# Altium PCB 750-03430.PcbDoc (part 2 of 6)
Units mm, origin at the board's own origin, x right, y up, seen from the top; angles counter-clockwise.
Board outline 141.61 x 63.5 mm, 6 copper layers (Top Layer, L2, L3, L4, L5, Bottom Layer), stack 1.557 mm thick; 401 components, 285 nets, 1356 pads, 1712 vias.
Unrouted connection lines stored in the file: 45.
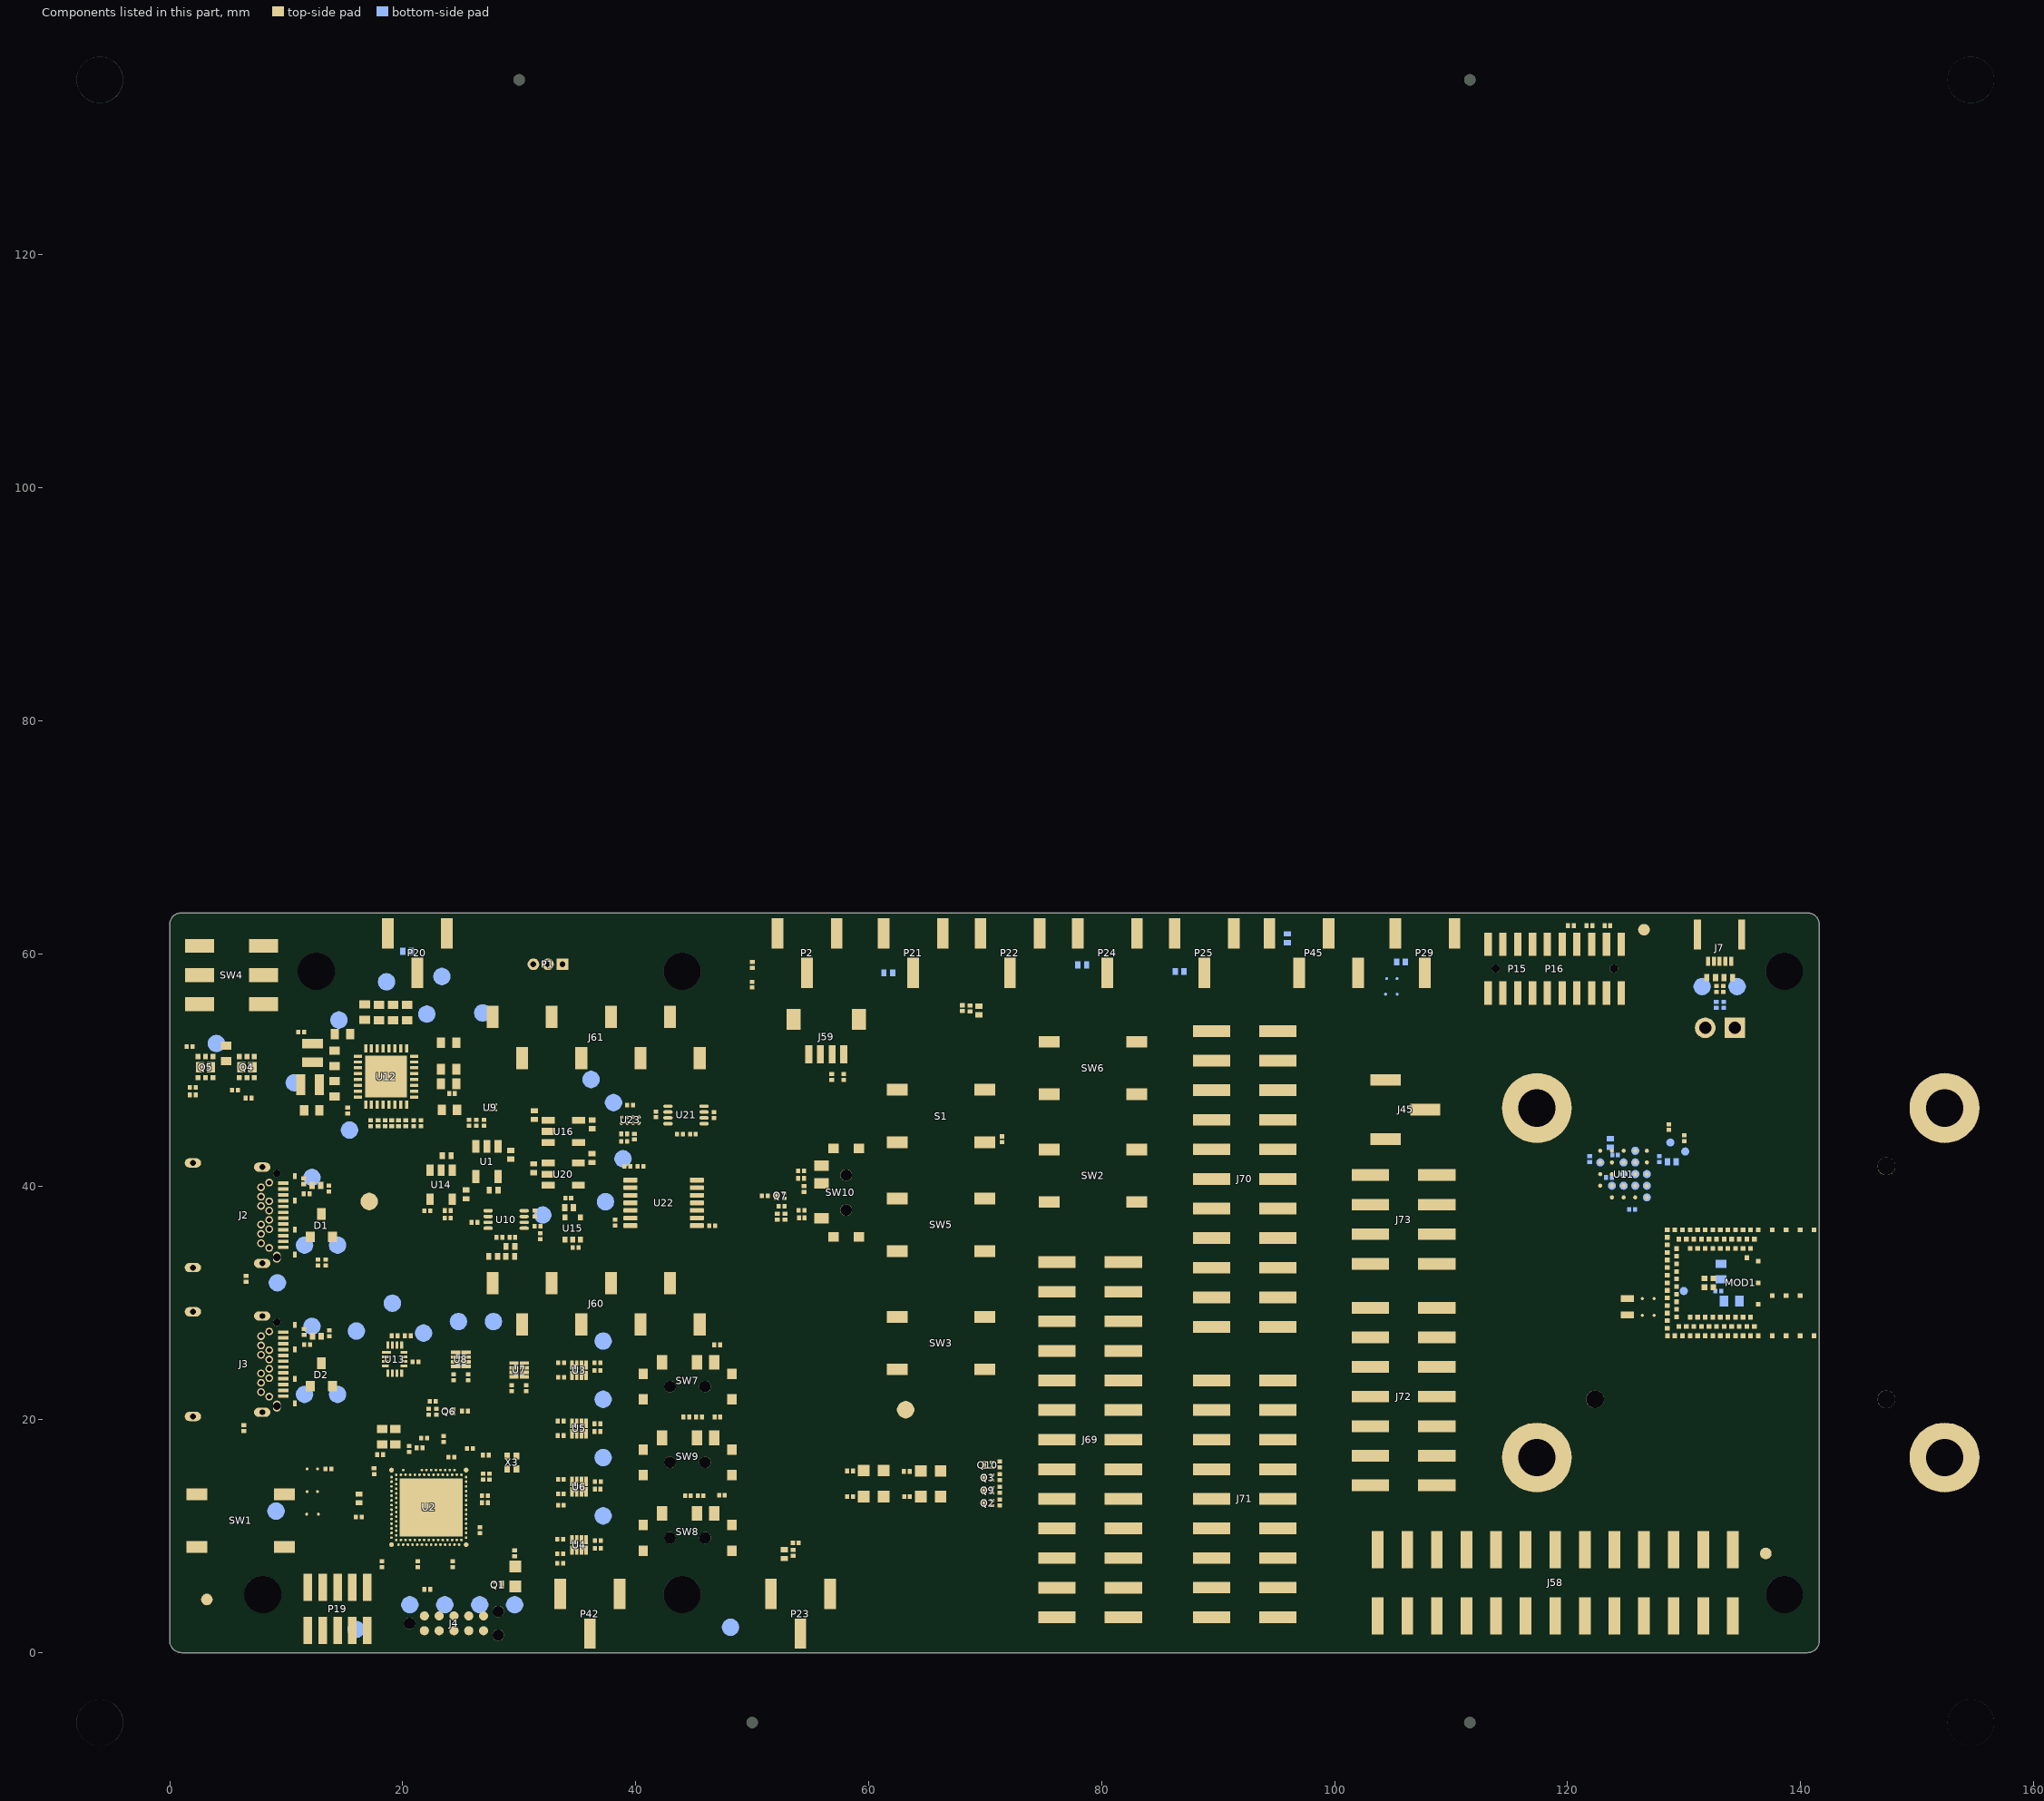
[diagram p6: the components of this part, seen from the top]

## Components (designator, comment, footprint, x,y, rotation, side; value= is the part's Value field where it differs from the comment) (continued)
TP45 "SMT, 1.5mm, Test Pad" "Test Point, SMT 1.5mm Round" 37.208,26.746 r180 bottom
TP46 "SMT, 1.5mm, Test Pad" "Test Point, SMT 1.5mm Round" 37.208,11.746 r180 bottom
TP51 "SMT, 1.5mm, Test Pad" "Test Point, SMT 1.5mm Round" 37.208,21.746 r180 bottom
TP52 "SMT, 1.5mm, Test Pad" "Test Point, SMT 1.5mm Round" 37.208,16.746 r180 bottom
TP58 "SMT, 1.5mm, Test Pad" "Test Point, SMT 1.5mm Round" 27.79,28.423 r270 bottom
TP59 "SMT, 1.5mm, Test Pad" "Test Point, SMT 1.5mm Round" 24.79,28.423 r270 bottom
TP60 "SMT, 1.5mm, Test Pad" "Test Point, SMT 1.5mm Round" 32.026,37.567 r180 bottom
TP61 "SMT, 1.5mm, Test Pad" "Test Point, SMT 1.5mm Round" 21.79,27.432 r270 bottom
TP62 "SMT, 1.5mm, Test Pad" "Test Point, SMT 1.5mm Round" 9.126,12.15 r180 bottom
TP73 "SMT, 1.5mm, Test Pad" "Test Point, SMT 1.5mm Round" 23.365,58.039 r180 bottom
TP82 "SMT, 1.5mm, Test Pad" "Test Point, SMT 1.5mm Round" 19.115,29.997 r180 bottom
TP84 "SMT, 0.7mm, Test Pad" "Test Point, SMT 0.7mm Round" 129.972,31.045 r90 bottom
TP87 "SMT, 1.5mm, Test Pad" "Test Point, SMT 1.5mm Round" 14.526,54.305 r90 bottom
TP88 "SMT, 1.5mm, Test Pad" "Test Point, SMT 1.5mm Round" 22.07,54.813 r0 bottom
U1 "On Semiconductor, NCV8114ASN180T1G" "SOT23_5, Height 1.1mm" 27.234,42.173 r270 top value=NCV8114ASN180T1G
U2 "Nordic, nRF5340-QKAA" "Nordic, nRF5340-QKAA" 22.445,12.474 r0 top value=nRF5340-QKAA
U3 "TI, TXB0302DQMR" "X2SON, 8-Leads, SMD" 35.145,24.246 r90 top value=TXB0302DQMR
U4 "TI, TXB0302DQMR" "X2SON, 8-Leads, SMD" 35.145,9.246 r90 top value=TXB0302DQMR
U5 "TI, TXB0302DQMR" "X2SON, 8-Leads, SMD" 35.145,19.246 r90 top value=TXB0302DQMR
U6 "TI, TXB0302DQMR" "X2SON, 8-Leads, SMD" 35.145,14.246 r90 top value=TXB0302DQMR
U7 "TI, TXB0302DQMR" "X2SON, 8-Leads, SMD" 29.995,24.264 r180 top value=TXB0302DQMR
U8 "TI, TXB0302DQMR" "X2SON, 8-Leads, SMD" 24.995,25.171 r180 top value=TXB0302DQMR
U9 "Toshiba, TCK111G,LF" "WLCSP-6, 1.0mm x 1.5mm, 0.5mm pitch" 27.51,46.795 r270 top value=TCK111G,LF
U10 "TI, TXB0102DCUR" VFSOP8_2x2.3 28.881,37.186 r270 top value=TXB0102DCUR
U11 "Macronix, MX25UW6345GXDI00" "BGA 24, 6mmx8mm, Hight 1.2mm" 124.803,41.079 r90 top value=MX25UW6345GXDI00
U12 "Nordic, nPM1300-QEAA" "QFN32, 5x5, Pitch 0.5mm, Height 1mm" 18.574,49.45 r0 top value=nPM1300-QEAA
U13 "ON Semi, FSA2466UMX" "UQFN16, 2.6x1.8, Pitch 0.4mm, Height 0.5mm" 19.316,25.196 r0 top value=FSA2466UMX
U14 "Richtek, RT9187BGB" "SOT23-5, Height1.3mm" 23.299,40.168 r270 top value=RT9187BGB
U15 "TI, SN74LV1T34DCKR" SC70-5 34.598,36.419 r0 top value=SN74LV1T34DCKR
U16 "On Semiconductor, NCV8114ASN180T1G" "SOT23_5, Height 1.1mm" 33.796,44.742 r0 top value=NCV8114ASN180T1G
U20 "On Semiconductor, NCV8114ASN180T1G" "SOT23_5, Height 1.1mm" 33.787,41.075 r0 top value=NCV8114ASN180T1G
U21 "TI, TXB0102DCUR" VFSOP8_2x2.3 44.321,46.155 r270 top value=TXB0102DCUR
U22 "TI, TXB0104PWR" "SOP-14, Body 5.1x4.5mm, Pitch 0.65mm, IPC High Density" 42.404,38.611 r180 top value=TXB0104PWR
U23 "TI,  TXS0102YZPR" "TI, TXS0102YZPR" 39.523,45.718 r270 top value=TXS0102YZPR
X2 "Siward, XTL741-S999-506" "Crystal, 2 pin, 2.0mm x 1.2mm" 125.122,29.703 r270 top value=32.768kHz
X3 "Siward, XTL901200-L146-014" "Crystal, 4 pin, 1.6mm x 1.2mm" 29.37,16.329 r90 top value=32.000000MHz

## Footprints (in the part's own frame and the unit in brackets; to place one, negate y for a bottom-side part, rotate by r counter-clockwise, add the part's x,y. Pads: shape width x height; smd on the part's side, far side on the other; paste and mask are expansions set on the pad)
"1P27MM-2X5 Male"#1 [mm] "Pin Header, SMT, 2X5P, Pitch 1.27mm, 180 Degree(30/20/25)"
  rect 0.63x2 smd: 1(-2.54,-2.1) 2(-2.54,2.1) 3(-1.27,-2.1) 4(-1.27,2.1) 5(0,-2.1) 6(0,2.1) 7(1.27,-2.1) 8(1.27,2.1) 9(2.54,-2.1) 10(2.54,2.1)
  silkscreen extent -3.4,-2.03 3.43,2.02, body extent -3.17,-2.75 3.17,2.75, height 5.7
"1P27MM-2X5 Male"#2 [mm] "Pin Header, SMT, 2X5P, Pitch 1.27mm, 180 Degree(30/20/25)"
  rect 0.74x2.3 smd: 1(-2.54,-1.85) 2(-2.54,1.85) 3(-1.27,-1.85) 4(-1.27,1.85) 5(0,-1.85) 6(0,1.85) 7(1.27,-1.85) 8(1.27,1.85) 9(2.54,-1.85) 10(2.54,1.85)
  silkscreen extent -3.4,-2.03 3.43,2.02, body extent -3.17,-2.75 3.17,2.75, height 5.7
"1P27MM-2X10 Male" [mm] "Pin Header, SMT, 2X10P, Pitch 1.27mm, 180 Degree(30/20/25)"
  rect 2x0.63 smd: 1(-2.1,5.715) 2(2.1,5.715) 3(-2.1,4.445) 4(2.1,4.445) 5(-2.1,3.175) 6(2.1,3.175) 7(-2.1,1.905) 8(2.1,1.905) 9(-2.1,0.635) 10(2.1,0.635) 11(-2.1,-0.635) 12(2.1,-0.635) 13(-2.1,-1.905) 14(2.1,-1.905) 15(-2.1,-3.175) 16(2.1,-3.175) 17(-2.1,-4.445) 18(2.1,-4.445) 19(-2.1,-5.715) 20(2.1,-5.715)
  round 0.7 hole 0.7 unplated mask+0.051: 21(0,5.08) 22(0,-5.08)
  silkscreen extent -0.5,-6.35 0.5,6.35, body extent -2.75,-6.35 2.75,6.35, height 5.5
"2P54MM-1X2, male" [mil] "Pin Header, DIP, 1X2P, Pitch 2.54mm, 180 Degree(60/25/30)"
  rect 70x70 / inner round 70 / far side rect 70x70 hole 42: 1(-50,0)
  round 70 hole 42: 2(50,0)
  silkscreen extent -103,-54 105,54, body extent -100,-49 100,49, height 335
"2P54MM-1X3, male" [mm] "Pin Header, SMT, male, 1X3, Pitch 2.54mm, PHY 0.64mm, 180 (60/33)"
  rect 1x2.6 smd: 1(-2.54,-1.7) 2(0,1.7) 3(2.54,-1.7)
  silkscreen extent -3.81,-3.45 3.81,3.35, body extent -3.81,-2.5 3.81,2.5, height 9.82
"2P54MM-1X4, male" [mm] "Pin Header, SMT, male, 1X4, Pitch 2.54mm, PHY 0.64mm, 180 (60/33)"
  rect 1x2.6 smd: 1(-3.81,1.7) 2(-1.27,-1.7) 3(1.27,1.7) 4(3.81,-1.7)
  silkscreen extent -5.08,-3.45 5.08,3.35, body extent -5.08,-2.5 5.08,2.5, height 9.82
"2P54MM-1X8, Female" [mil] "Pin Header, SMT, Female, 1X8, Pitch 2.54mm, PHY 0.64mm, 180°"
  rect 40.16x75 smd: 1(-350,70) 2(-250,-70) 3(-150,70) 4(-50,-70) 5(50,70) 6(150,-70) 7(250,70) 8(350,-70)
  silkscreen extent -400,-114 400,114, body extent -400,-104 400,104, height 390
"2P54MM-2X4 Male" [mm] "Pin Header, SMT, 2X4P, Pitch 2.54mm, 180 Degree(60/33)"
  rect 1x3.2 smd: 1(-3.81,-2.85) 2(-3.81,2.85) 3(-1.27,-2.85) 4(-1.27,2.85) 5(1.27,-2.85) 6(1.27,2.85) 7(3.81,-2.85) 8(3.81,2.85)
  silkscreen extent -5.08,-2.54 5.08,2.54, body extent -5.03,-3.75 5.03,3.75, height 9.7
"2P54MM-2X7 Male" [mm] "Pin Header, SMT, 2X7P, Pitch 2.54mm, 180 Degree(60/33)"
  rect 1x3.2 smd: 1(-7.62,-2.85) 2(-7.62,2.85) 3(-5.08,-2.85) 4(-5.08,2.85) 5(-2.54,-2.85) 6(-2.54,2.85) 7(0,-2.85) 8(0,2.85) 9(2.54,-2.85) 10(2.54,2.85) 11(5.08,-2.85) 12(5.08,2.85) 13(7.62,-2.85) 14(7.62,2.85)
  silkscreen extent -8.89,-2.54 8.89,2.54, body extent -8.84,-3.75 8.84,3.75, height 9.7
"2P54MM-2X9 Male" [mm] "Pin Header, SMT, 2X9P, Pitch 2.54mm, 180 Degree(60/33)"
  rect 1x3.2 smd: 1(-10.16,-2.85) 2(-10.16,2.85) 3(-7.62,-2.85) 4(-7.62,2.85) 5(-5.08,-2.85) 6(-5.08,2.85) 7(-2.54,-2.85) 8(-2.54,2.85) 9(0,-2.85) 10(0,2.85) 11(2.54,-2.85) 12(2.54,2.85) 13(5.08,-2.85) 14(5.08,2.85) 15(7.62,-2.85) 16(7.62,2.85) 17(10.16,-2.85) 18(10.16,2.85)
  silkscreen extent -11.43,-2.54 11.43,2.54, body extent -11.38,-3.75 11.38,3.75, height 9.7
"2P54MM-2X11 Male" [mm] "Pin Header, SMT, 2X11P, Pitch 2.54mm, 180 Degree(60/33)"
  rect 1x3.2 smd: 1(-12.7,-2.85) 2(-12.7,2.85) 3(-10.16,-2.85) 4(-10.16,2.85) 5(-7.62,-2.85) 6(-7.62,2.85) 7(-5.08,-2.85) 8(-5.08,2.85) 9(-2.54,-2.85) 10(-2.54,2.85) 11(0,-2.85) 12(0,2.85) 13(2.54,-2.85) 14(2.54,2.85) 15(5.08,-2.85) 16(5.08,2.85) 17(7.62,-2.85) 18(7.62,2.85) 19(10.16,-2.85) 20(10.16,2.85) 21(12.7,-2.85) 22(12.7,2.85)
  silkscreen extent -13.97,-2.54 13.97,2.54, body extent -13.92,-3.75 13.92,3.75, height 9.7
2P54MM-2X13Male [mm] "Pin Header, SMT, 2X13P, Pitch 2.54mm, 180 Degree(60/33)"
  rect 1x3.2 smd: 1(-15.239,-2.849) 2(-15.239,2.851) 3(-12.699,-2.849) 4(-12.699,2.851) 5(-10.159,-2.849) 6(-10.159,2.851) 7(-7.619,-2.849) 8(-7.619,2.851) 9(-5.079,-2.849) 10(-5.079,2.851) 11(-2.539,-2.849) 12(-2.539,2.851) 13(0.001,-2.849) 14(0.001,2.851) 15(2.541,-2.849) 16(2.541,2.851) 17(5.081,-2.849) 18(5.081,2.851) 19(7.621,-2.849) 20(7.621,2.851) 21(10.161,-2.849) 22(10.161,2.851) 23(12.701,-2.849) 24(12.701,2.851) 25(15.239,-2.851) 26(15.239,2.849)
  silkscreen extent -16.51,-2.54 16.51,2.54, body extent -16.47,-3.75 16.45,3.75, height 9.7
"BGA 24, 6mmx8mm, Hight 1.2mm" [mm] "BGA 24, 24-Leads, Body 6mmx8mm, Height 1.2mm, Pitch 1mm"
  round 0.35 smd mask+0.051: A2(-1,2) A3(0,2) A5(2,2) B1(-2,1) B5(2,1) C5(2,0) D1(-2,-1) E4(1,-2)
  round 0.35 smd mask+0: A4(1,2) B2(-1,1) B3(0,1) B4(1,1) C1(-2,0) C2(-1,0) C3(0,0) C4(1,0) D2(-1,-1) D3(0,-1) D4(1,-1) D5(2,-1) E1(-2,-2) E2(-1,-2) E3(0,-2) E5(2,-2)
  silkscreen extent -3.28,-4 3,4.27, body extent -3,-4 3,4, height 1.21
"C&K, JS202011SCQN" [mm] "Switch Slide, SMT, DPDT, 9mm x 3.6mm, Height 5.5mm"
  rect 1.2x2.5 smd mask+0.051: 1(-2.5,-2.75) 2(0,-2.75) 3(2.5,-2.75) 4(-2.5,2.75) 5(0,2.75) 6(2.5,2.75)
  silkscreen extent -4.5,-4.23 4.5,4.23, body extent -4.5,-3.75 4.5,3.75, height 5.5
"Cap, C0201, Height 0.3mm" [mm] "Capacitor, C0201, Body 0.6 x 0.3mm, Height 0.3mm"
  rect 0.352x0.402 smd paste-0.051 mask-0.051: 1(-0.25,0) 2(0.25,0)
  silkscreen extent -0.5,-0.27 0.5,0.28, body extent -0.3,-0.15 0.3,0.15, height 0.3
"Chip, 0603, RF" [mil] "Chip, 0603 RF, Body 1.6x0.8mm, Height 0.8mm, NON IPC RF"
  rect 28x36 smd paste-2 mask-2: 1(-26,0) 2(26,0)
  silkscreen extent -43,-21 43,21, body extent -32,-16 31,16, height 31
"Chip. 0402, RF" [mm] "Chip, 0402 RF, Body 1.0x0.5mm, Height 0.5mm, NON IPC RF"
  rect 0.452x0.602 smd paste-0.051 mask-0.051: 1(-0.375,0) 2(0.375,0)
  silkscreen extent -0.67,-0.37 0.67,0.37, body extent -0.5,-0.25 0.5,0.25, height 0.5
"CON WAFER, 1X4P" [mm] "CON WAFER, SMT, 1X4P, Pitch 1.0mm, 180 Degree"
  rect 0.6x1.55 smd mask+0.051: 1(-1.5,-1.488) 2(-0.5,-1.488) 3(0.5,-1.488) 4(1.5,-1.488)
  rect 1.2x1.8 smd mask+0.051: 5(-2.8,1.487) 6(2.8,1.487)
  silkscreen extent -3.75,-2.51 3.75,2.74, body extent -3,-1.41 3,2.19, height 4.35
"Contact, SS-B95A-W-S246" [mm] "Switch Slide, SMT, 1P2T, 7.8mm x 3.7mm, Height 3.4mm"
  rect 0.9x1.25 smd mask+0.051: 1(-2.2,1.6) 2(0.8,1.6) 3(2.3,1.6)
  rect 0.8x0.9 smd mask+0.051: 4(-3.8,0.6) 5(-3.8,-1.6) 6(3.8,0.6) 7(3.8,-1.6)
  round 1 hole 1 unplated mask+0.051: 8(-1.5,-0.5) 9(1.5,-0.5)
  silkscreen extent -4.45,-2.23 4.43,2.49, body extent -3.91,-1.86 3.91,1.84, height 3.4
"Crystal, 2 pin, 2.0mm x 1.2mm" [mm] "Crystal, 2 pin, Body 2.0mm x 1.2mm , Height 0.6mm"
  rect 0.6x1.1 smd mask+0.051: 1(-0.7,0) 2(0.7,0)
  silkscreen extent -1.15,-0.7 1.15,0.7, body extent -1,-0.6 1,0.6, height 0.6
"Crystal, 4 pin, 1.6mm x 1.2mm" [mm] "Crystal, 4 pin, Body 1.6mm x 1.2mm, Height 0.4mm"
  rect 0.6x0.5 smd: 1(-0.55,-0.4) 2(0.55,-0.4) 3(0.55,0.4) 4(-0.55,0.4)
  silkscreen extent -1.02,-0.82 1.02,0.82, body extent -0.8,-0.6 0.8,0.6, height 0.31
DFN1006-3 [mm] "DFN1006-3, 3-Leads, Body 0.6x1mm, Height 0.4mm"
  rect 0.4x0.25 smd mask+0.051: 1(-0.35,0.225) 2(-0.35,-0.225)
  rect 0.4x0.7 smd mask+0.051: 3(0.35,0)
  silkscreen extent -0.67,-0.45 0.67,0.45, body extent -0.5,-0.3 0.5,0.3, height 0.41
"Everlight, LED0603, Blue" [mm] "LED, SMT, Body 1.6 x 0.8 mm, 0.4mm Thickness"
  rect 1x1 smd: 1(-0.85,0) 2(0.85,0)
  silkscreen extent -0.57,0.81 0.86,1.41, body extent -0.8,-0.4 0.8,0.4, height 0.4
"FB, FB0402, RF" [mm] "Ferrite Bead, FB0402, Body 1.0 x 0.5mm, Height 0.55mm"
  rect 0.452x0.602 smd paste-0.051 mask-0.051: 1(-0.375,0) 2(0.375,0)
  silkscreen extent -0.67,-0.37 0.67,0.37, body extent -0.52,-0.27 0.53,0.28, height 0.55
Fiducial [mm] "Keepout Fiducial"
  round 1 smd paste-10 mask+0.5: 0(0,0)
  Top Layer keep-out circle w0.01: c0,0 r0.991
"IND, 0806, Height 1.0mm" [mm] "Chip Inductor, Body 2.0x1.6mm, Height 1.0mm"
  rect 0.8x1.8 smd mask+0.051: 1(-0.8,0) 2(0.8,0)
  silkscreen extent -1.4,-1.11 1.4,1.11, body extent -1,-0.8 1,0.8, height 1
"Kingconn, 7USB31-F0-0029" [mm] "USB, 24P, C TYPE"
  oval 0.8x1.4 hole 0.5 slot 1.1 at 90 deg mask+0.051: 1(-4.13,1.575) 2(4.13,1.575) 3(-4.49,-4.375) 4(4.49,-4.375)
  rect 0.5x0.3 smd mask+0.051: 5(-3.375,4.375) 6(-1.25,4.375) 7(1.25,4.375) 8(3.375,4.375)
  round 0.65 hole 0.65 unplated mask+0.051: 9(-3.6,2.825)
  oval 0.95x0.65 hole 0.65 slot 0.95 at 0 deg unplated mask+0.051: 10(3.6,2.825)
  rect 0.3x0.9 smd mask+0.051: A1(-2.75,3.385) A2(-2.25,3.385) A3(-1.75,3.385) A4(-1.25,3.385) A5(-0.75,3.385) A6(-0.25,3.385) A7(0.25,3.385) A8(0.75,3.385) A9(1.25,3.385) A10(1.75,3.385) A11(2.25,3.385) A12(2.75,3.385)
  round 0.66 hole 0.4 mask+0.051: B1(2.8,2.175) B2(2.4,1.475) B3(1.6,1.475) B4(1.2,2.175) B5(0.8,1.475) B6(0.4,2.175) B7(-0.4,2.175) B8(-0.8,1.475) B9(-1.2,2.175) B10(-1.6,1.475) B11(-2.4,1.475) B12(-2.8,2.175)
  silkscreen extent -4.59,-6.38 4.59,4.47, body extent -4.62,-6.38 4.62,4.47, height 3.39
"Laird, BL54H20 Module, Chip Antenna, Platform Side" [mm] "Laird, BL54H20 Module, Chip Antenna, Platform Side"
  rrect0% 0.4x0.4 smd mask+0: 1(1.6,-4.55) 14(-1.325,-3.75) 18(-2.3,-2.95) 33(-6.2,-4.55) 40(-5.4,-1.625) 48(-5.4,0.975) 57(-6.2,4.55) 80(-0.35,2.95) 89(1.6,4.55) 93(6.4,-4.55) 94(5.2,-4.55) 95(4,-4.55) 96(2.8,-4.55) 97(5.2,-1.1) 98(4,-1.1) 99(2.8,-1.1) 100(6.4,4.55) 101(5.2,4.55) 102(4,4.55) 103(2.8,4.55)
  rrect0% 0.4x0.4 smd mask+0.051: 2(1.275,-3.75) 3(0.95,-2.95) 4(0.95,-4.55) 5(0.625,-3.75) 6(0.3,-2.95) 7(0.3,-4.55) 8(-0.025,-3.75) 9(-0.35,-2.95) 10(-0.35,-4.55) 11(-0.675,-3.75) 12(-1,-2.95) 13(-1,-4.55) 15(-1.65,-2.95) 16(-1.65,-4.55) 17(-1.975,-3.75) 19(-2.3,-4.55) 20(-2.625,-3.75) 21(-2.95,-2.95) 22(-2.95,-4.55) 23(-3.275,-3.75) 24(-3.6,-2.95) 25(-3.6,-4.55) 26(-3.925,-3.75) 27(-4.25,-2.95) 28(-4.25,-4.55) 29(-4.575,-3.75) 30(-4.9,-4.55) 32(-5.55,-4.55) 34(-6.2,-3.9) 35(-6.2,-3.25) 36(-5.4,-2.925) 37(-6.2,-2.6) 38(-5.4,-2.275) 39(-6.2,-1.95) 41(-6.2,-1.3) 42(-5.4,-0.975) 43(-6.2,-0.65) 44(-5.4,-0.325) 45(-6.2,0) 46(-5.4,0.325) 47(-6.2,0.65) 49(-6.2,1.3) 50(-5.4,1.625) 51(-6.2,1.95) 52(-5.4,2.275) 53(-6.2,2.6) 54(-5.4,2.925) 55(-6.2,3.25) 56(-6.2,3.9) 58(-5.55,4.55) 60(-4.9,4.55) 61(-4.575,3.75) 62(-4.25,2.95) 63(-4.25,4.55) 64(-3.925,3.75) 65(-3.6,2.95) 66(-3.6,4.55) 67(-3.275,3.75) 68(-2.95,2.95) 69(-2.95,4.55) 70(-2.625,3.75) 71(-2.3,2.95) 72(-2.3,4.55) 73(-1.975,3.75) 74(-1.65,2.95) 75(-1.65,4.55) 76(-1.325,3.75) 77(-1,2.95) 78(-1,4.55) 79(-0.675,3.75) 81(-0.35,4.55) 82(-0.025,3.75) 83(0.3,2.95) 84(0.3,4.55) 85(0.625,3.75) 86(0.95,2.95) 87(0.95,4.55) 88(1.275,3.75) 104(0.625,2.15)
  rect 0.4x0.4 smd mask+0: 31(-5.225,-3.75) 90(1.6,1.85) 91(1.6,0) 92(1.6,-1.85)
  rect 0.4x0.4 smd mask+0.051: 59(-5.225,3.75)
  rect 0.5x0.5 smd mask+0.051: G1(-3,0.375) G2(-2.25,0.375) G3(-3,-0.375) G4(-2.25,-0.375)
  Top Layer pour cut-out: 1.85,4.175 1.85,-0.825 6.85,-0.825 6.85,4.175
  silkscreen extent -6.65,-5 6.85,5, body extent -6.4,-4.75 6.6,4.75, height 0.01
LOGO_MICROBUS_GTO_W12.24 [mm] "Logo microBUS GTO width 12.24 (200625)"
  silkscreen extent 0,0 5.6,4.01
LOGO_QWIIC_GTO_W7.0 [mm] "Logo QWIIC GTO width 7.0 (200625)"
  silkscreen extent 0,0 6.95,2.22
"MCC, MCM2301-TP" [mm] "DFN2020-6, 8-Leads, Body 2.05x2.05mm, Height 0.85mm"
  rect 0.45x0.42 smd mask+0.051: 1(-0.905,0.65) 2(-0.905,0) 3(-0.905,-0.65) 4(0.905,-0.65) 5(0.905,0) 6(0.905,0.65)
  rect 0.92x0.71 smd mask+0.051: 3(0,-0.475) 6(0,0.475)
  silkscreen extent -1.27,-1.03 1.27,1.02, body extent -1.02,-1.03 1.02,1.05, height 0.86
"Molex, 0512810598" [mm] "5 Position FFC, FPC Connector"
  rect 0.8x0.35 smd mask+0.051: 1(1.919,1) 2(1.919,0.5) 3(1.919,0) 4(1.919,-0.5) 5(1.919,-1)
  rect 2.6x0.6 smd mask+0.051: 6(-0.381,-1.9) 7(-0.381,1.9)
  silkscreen extent -2.03,-2.4 2.02,2.4, body extent -1.91,-2.3 2.15,2.3, height 1.2
"Molex, 0530480310" [mm] "THD, 3-Leads, Righ Angle, Body 5.5x3.2mm, Pitch 1.25mm"
  rect 1x1 hole 0.5: 1(-1.25,0)
  round 1 hole 0.5: 2(0,0) 3(1.25,0)
  silkscreen extent -2.75,-4.37 3.43,1.13, body extent -2.75,-4.43 2.75,1.07, height 3.4
"Nordic, nRF5340-QKAA" [mm] "Nordic, nRF5340-QKAA, AQFN-94, 7mm x 7mm"
  rect 5.4x5 smd paste-5 mask+0.05: 104(0,0)
  round 0.4 smd paste+0.012 mask+0.05: A1(-3.4,3.2) A31(3,3.2) AL1(-3.4,-3.2) AL31(3,-3.2)
  round 0.225 smd paste+0.012 mask+0.05: A5(-2.4,3.2) A13(-0.8,3.2) A15(-0.4,3.2) A17(0,3.2) A19(0.4,3.2) A21(0.8,3.2) A23(1.2,3.2) A25(1.6,3.2) A27(2,3.2) AA1(-3.4,-1) AA31(3,-1) AB2(-3,-1.2) AC1(-3.4,-1.4) AC31(3,-1.4) AD2(-3,-1.6) AE1(-3.4,-1.8) AE31(3,-1.8) AF2(-3,-2) AG1(-3.4,-2.2) AG31(3,-2.2) AH2(-3,-2.4) AJ1(-3.4,-2.6) AJ31(3,-2.6) AK2(-3,-2.8) AK4(-2.6,-2.8) AK6(-2.2,-2.8) AK8(-1.8,-2.8) AK10(-1.4,-2.8) AK12(-1,-2.8) AK14(-0.6,-2.8) AK16(-0.2,-2.8) AK18(0.2,-2.8) AK20(0.6,-2.8) AK22(1,-2.8) AK24(1.4,-2.8) AK26(1.8,-2.8) AK28(2.2,-2.8) AK30(2.6,-2.8) AL3(-2.8,-3.2) AL5(-2.4,-3.2) AL7(-2,-3.2) AL9(-1.6,-3.2) AL11(-1.2,-3.2) AL13(-0.8,-3.2) AL15(-0.4,-3.2) AL17(0,-3.2) AL19(0.4,-3.2) AL21(0.8,-3.2) AL23(1.2,-3.2) AL25(1.6,-3.2) AL27(2,-3.2) AL29(2.4,-3.2) B2(-3,2.8) B4(-2.6,2.8) B6(-2.2,2.8) B8(-1.8,2.8) B10(-1.4,2.8) B12(-1,2.8) B14(-0.6,2.8) B16(-0.2,2.8) B18(0.2,2.8) B20(0.6,2.8) B22(1,2.8) B24(1.4,2.8) B26(1.8,2.8) B28(2.2,2.8) B30(2.6,2.8) C1(-3.4,2.6) C31(3,2.6) D2(-3,2.4) E1(-3.4,2.2) E31(3,2.2) F2(-3,2) G1(-3.4,1.8) G31(3,1.8) H2(-3,1.6) J1(-3.4,1.4) J31(3,1.4) K2(-3,1.2) L1(-3.4,1) L31(3,1) M2(-3,0.8) N1(-3.4,0.6) N31(3,0.6) P2(-3,0.4) R1(-3.4,0.2) R31(3,0.2) T2(-3,0) U1(-3.4,-0.2) U31(3,-0.2) V2(-3,-0.4) W1(-3.4,-0.6) W31(3,-0.6) Y2(-3,-0.8)
  rrect50% 1.1x1 on Top Paste: ""(-1.95,-1.8) ""(-1.95,-0.6) ""(-1.95,0.6) ""(-1.95,1.8) ""(-0.65,-1.8) ""(-0.65,-0.6) ""(-0.65,0.6) ""(-0.65,1.8) ""(0.65,-1.8) ""(0.65,-0.6) ""(0.65,0.6) ""(0.65,1.8) ""(1.95,-1.8) ""(1.95,-0.6) ""(1.95,0.6) ""(1.95,1.8)
  silkscreen extent -4.42,-3.6 3.4,3.6, body extent -3.7,-3.5 3.3,3.5, height 0.85
"QFN32, 5x5, Pitch 0.5mm, Height 1mm" [mm] "QFN, 32 pin, 5mm x 5mm, Pitch 0.5mm, Height 1mm"
  rect 0.7x0.28 smd mask+0.051: 1(-2.4,1.751)
  rect 0.7x0.27 smd mask+0.051: 2(-2.4,1.251) 3(-2.4,0.751) 4(-2.4,0.25) 5(-2.4,-0.25) 6(-2.4,-0.751) 7(-2.4,-1.251) 8(-2.4,-1.751) 17(2.4,-1.751) 18(2.4,-1.251) 19(2.4,-0.751) 20(2.4,-0.25) 21(2.4,0.25) 22(2.4,0.751) 23(2.4,1.251) 24(2.4,1.751)
  rect 0.27x0.7 smd mask+0.051: 9(-1.751,-2.4) 10(-1.251,-2.4) 11(-0.751,-2.4) 12(-0.25,-2.4) 13(0.25,-2.4) 14(0.751,-2.4) 15(1.251,-2.4) 16(1.751,-2.4) 25(1.751,2.4) 26(1.251,2.4) 27(0.751,2.4) 28(0.25,2.4) 29(-0.25,2.4) 30(-0.751,2.4) 31(-1.251,2.4) 32(-1.751,2.4)
  rect 3.607x3.607 smd paste-100 mask+0.051: 33(0,0)
  silkscreen extent -2.68,-2.68 2.68,2.68, body extent -2.55,-2.55 2.55,2.55, height 1
"RES, R0201, Height 0.23mm" [mm] "Resister, R0201, Height 0.23mm"
  rect 0.352x0.402 smd paste-0.051 mask-0.051: 1(-0.25,0) 2(0.25,0)
  silkscreen extent -0.5,-0.28 0.5,0.28, body extent -0.3,-0.15 0.3,0.15, height 0.23
"RES, R0402, RF" [mm] "Resister, R0402, Height 0.35mm"
  rect 0.452x0.602 smd paste-0.051 mask-0.051: 1(-0.375,0) 2(0.375,0)
  silkscreen extent -0.67,-0.37 0.67,0.37, body extent -0.5,-0.25 0.5,0.25, height 0.35
SC70-5 [mil] "SC70, 5 pin, 2.0x1.25mm, Height 1.1mm"
  rect 16x20 smd: 1(-26,-37.5) 2(0,-37.5) 3(26,-37.5) 4(26,37.5) 5(-26,37.5)
  silkscreen extent -45,-30 45,31, body extent -41,-45 41,45, height 39
"Screw Hole, Hole 1.524mm, Dia 1.524mm" [mil] "Screw Hole, Hole 1.524mm, Dia 1.524mm"
  round 60 hole 60 unplated: 1(0,0)
"Screw Hole, Hole 3.2mm, Dia 6mm" [mm] "Screw Hole, Hole 3.2mm, Dia 6mm"
  round 6 hole 3.2 unplated: 0(0,0)
  body extent -3,-3 3,3
"Solder Bridge Closed" [mil] "Solderbridge Closed"
  round 10 smd paste-10: 1(-19.69,0) 2(19.68,0)
  Top Layer region: -5.91,-19.69 -9.84,-19.69 -17.38,-18.19 -23.76,-13.92 -28.03,-7.53 -29.53,0 -29.53,0 -28.03,7.53 -23.76,13.92 -17.38,18.19 -9.84,19.69 -9.84,19.69 -5.91,19.69
  Top Layer region: 5.91,19.69 9.84,19.69 17.38,18.19 23.76,13.92 28.03,7.53 29.53,0 29.53,0 28.03,-7.53 23.76,-13.92 17.38,-18.19 9.84,-19.69 9.84,-19.69 5.91,-19.69
  Top Layer lines w9.84: -5.91,0 5.91,0
"Solder Bridge Open" [mil] "WTS Solderbridge Open"
  round 10 smd paste-10: 1(-17.5,0) 2(17.5,0)
  Top Layer region: 6.12,19.69 10.06,19.69 17.59,18.19 23.98,13.92 28.25,7.53 29.74,0 29.74,0 28.25,-7.53 23.98,-13.92 17.59,-18.19 10.06,-19.69 10.06,-19.68 6.12,-19.68
  Top Layer region: -5.69,-19.68 -9.63,-19.68 -17.16,-18.19 -23.55,-13.92 -27.81,-7.53 -29.31,0 -29.31,0 -27.81,7.53 -23.55,13.92 -17.16,18.19 -9.63,19.69 -9.63,19.69 -5.69,19.69
"SOP-14, Body 5.1x4.5mm, Pitch 0.65mm, IPC High Density" [mm] "SOP, 14-Leads, Body 5.1x4.5mm, Pitch 0.65mm, IPC High Density"
  rrect25% 1.2x0.4 smd: 1(-2.85,1.95) 2(-2.85,1.3) 3(-2.85,0.65) 4(-2.85,0) 5(-2.85,-0.65) 6(-2.85,-1.3) 7(-2.85,-1.95) 8(2.85,-1.95) 9(2.85,-1.3) 10(2.85,-0.65) 11(2.85,0) 12(2.85,0.65) 13(2.85,1.3) 14(2.85,1.95)
  silkscreen extent -2.98,-2.55 1.85,2.82, body extent -3.21,-2.5 3.21,2.5, height 1
"SOT23-5, Height1.3mm" [mm] "SOT23, 5-Leads, Body 2.9x2.8mm, Pitch 0.95mm, Height1.3"
  rect 1x0.6 smd mask+0.051: 1(-1.25,0.95) 2(-1.25,0) 3(-1.25,-0.95) 4(1.25,-0.95) 5(1.25,0.95)
  silkscreen extent -0.9,-1.55 0.9,1.55, body extent -1.4,-1.45 1.4,1.45, height 1.3
"SOT23_5, Height 1.1mm" [mm] "SOT23, 5-Leads, Body 2.9x2.8mm, Height 1.1mm, Pitch 0.95mm"
  rect 1.1x0.6 smd mask+0.051: 1(-1.3,0.952) 2(-1.3,-0.002) 3(-1.3,-0.952) 4(1.3,-0.952) 5(1.3,0.952)
  silkscreen extent -0.8,-1.45 0.8,1.45, body extent -1.4,-1.45 1.4,1.45, height 1.1
SOT-23 [mil] "SOT23, 3-Leads, Body 2.92x1.4mm, Pitch 0.95mm"
  rect 30x40 smd mask+2: 1(0,38.5)
  rect 30x36 smd mask+2: 2(-37.4,-38.5) 3(37.4,-38.5)
  silkscreen extent -59,-28 59,29, body extent -59,-49 59,50, height 44
"Sullins, QPC02SXGN-RC" [mm] "Th, Shorting Jumper, 2.54mm, Black Open Top"
  body extent -2.5,-1.2 2.5,1.2, height 9.3
"TC2050-NL, TAG Test Interface" [mil] "TC2050-NL, TAG Test Interface"
  round 31 smd paste-78.74: 1(-100,-25) 2(-50,-25) 3(0,-25) 4(50,-25) 5(100,-25) 6(100,25) 7(50,25) 8(0,25) 9(-50,25) 10(-100,25)
  round 39 hole 39 unplated mask+2: 11(-150,0) 12(150,40) 13(150,-40)
  silkscreen extent -189,-83 193,87
"Test Point, SMT 0.7mm Round" [mm] "Test Point, SMT 0.7mm Round"
  round 0.7 smd paste-0.75: 1(0,0)
"Test Point, SMT 1.5mm Round" [mm] "Test Point, SMT 1.5mm Round"
  round 1.5 smd paste-1.6: 1(0,0)
  silkscreen extent -0.95,-0.95 0.95,0.95
"TI, TXS0102YZPR" [mm] "8-DSBGA (1.9x0.9)"
  round 0.33 smd paste-0.051 mask-0.051: A1(-0.25,0.75) A2(0.25,0.75) B1(-0.25,0.25) B2(0.25,0.25) C1(-0.25,-0.25) C2(0.25,-0.25) D1(-0.25,-0.75) D2(0.25,-0.75)
  silkscreen extent -1,-1.15 0.64,1.3, body extent -0.47,-0.98 0.47,0.98, height 0.51
"Touke, TS-06M-ASM-T" [mm] "Switch, Pushbutton, 6mm x 6mm"
  rect 1.8x1 smd: 1(-3.75,2.25) 2(3.75,2.25) 3(-3.75,-2.25) 4(3.75,-2.25)
  silkscreen extent -3.22,-3.5 3.22,3.4, body extent -3,-3.3 3,3.3, height 4
"UQFN16, 2.6x1.8, Pitch 0.4mm, Height 0.5mm" [mm] "UQFN, 16 pin, 2.6mm x 1.8mm, Pitch 0.4mm, Height 0.5mm"
  rect 0.8x0.24 smd mask+0.051: 1(-0.7,0.6)
  rect 0.6x0.24 smd mask+0.051: 2(-0.8,0.2) 3(-0.8,-0.2) 4(-0.8,-0.6) 9(0.8,-0.6) 10(0.8,-0.2) 11(0.8,0.2) 12(0.8,0.6)
  rect 0.24x0.6 smd mask+0.051: 5(-0.6,-1.2) 6(-0.2,-1.2) 7(0.2,-1.2) 8(0.6,-1.2) 13(0.6,1.2) 14(0.2,1.2) 15(-0.2,1.2) 16(-0.6,1.2)
  silkscreen extent -1.01,-1.39 1.01,1.42, body extent -0.95,-1.35 0.95,1.35, height 0.55
VFSOP8_2x2.3 [mm] "VFSOP, 8 pin, 2mm x 2.3mm"
  oval 0.3x0.8 smd mask+0.051: 1(-0.75,-1.55) 3(0.25,-1.55) 4(0.75,-1.55) 5(0.75,1.55) 6(0.25,1.55) 7(-0.25,1.55) 8(-0.75,1.55)
  oval 0.3x0.8 smd mask+0: 2(-0.25,-1.55)
  silkscreen extent -1.1,-0.85 1.1,0.8, body extent -1,-1.55 1,1.55, height 0.91
"WLCSP-6, 1.0mm x 1.5mm, 0.5mm pitch" [mm] "WLCSP-6, 1.0mm x 1.5mm, 0.5mm pitch"
  round 0.2 smd mask+0.075: A1(-0.25,0.5) B1(-0.25,0) C2(0.25,-0.5)
  round 0.2 smd mask+0: A2(0.25,0.5) B2(0.25,0) C1(-0.25,-0.5)
  silkscreen extent -0.6,-0.85 0.6,0.85, body extent -0.48,-0.73 0.48,0.72, height 0.47
"X2SON, 8-Leads, SMD" [mm] "X2SON, 8-Leads, Body 1.2mm x 1.8mm, Height 0.4mm, Pitch 0.4mm"
  rect 0.8x0.3 smd paste-0.051 mask-0.051: 1(-0.45,0.6) 2(-0.45,0.2) 3(-0.45,-0.2) 4(-0.45,-0.6) 5(0.45,-0.6) 6(0.45,-0.2) 7(0.45,0.2) 8(0.45,0.6)
  silkscreen extent -0.95,-0.9 0.95,0.9, body extent -0.6,-0.9 0.6,0.9, height 0.36

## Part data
C1: library part CMP-CAP-502-00099-1.10, "CAP, SMT, 0201, MLCC, 820pF, 25V, C0G, NP0, 5%", Manufacturer=Murata, Manufacturer Part Number=GRM0335C1E821JA01#, Operating Temperature=-55C~125C, Temp Coefficient="C0G, NP0", TOLERANCE=5%, Voltage=25V
C2 C9 C10 C13 C18 C20 C23 C24 C25 C26 C27 C28 C30 C34 C35 C36 C37 C41 C44 C46 C47 C48 C49 C50 C51 C53 C54 C55 C56 C57 C59 C60 C62 C63 C64 C71 C77 C87 C90: library part CMP-CAP-502-00106-1.11, "CAP, SMT, 0201, MLCC, 100nF, 10V, X7S, 10%", Manufacturer=Murata, Manufacturer Part Number=GRM033C71A104KE14#, Operating Temperature=-55C~125C, Temp Coefficient=X7S, TOLERANCE=10%, Voltage=10V
C3 C29 C58 C61 C67 C69 C70 C72 C96 C98 C99: library part CMP-CAP-502-00414-1.2, "CAP, SMT, 0603, MLCC, 10uF, 10V, X6S, 10%", Manufacturer=Murata, Manufacturer Part Number=GRM188C81A106KA73#, Operating Temperature=-55C~105C, Temp Coefficient=X6S, TOLERANCE=10%, Voltage=10V
C4 C8 C40: library part CMP-CAP-502-00198-1.11, "CAP, SMT, 0402, MLCC, 2.2uF, 10V, X7S, 10%", Manufacturer=Murata, Manufacturer Part Number=GRM155C71A225KE11#, Operating Temperature=-55C~125C, Temp Coefficient=X7S, TOLERANCE=10%, Voltage=10V
C5 C68: library part CMP-CAP-502-00117-1.11, "CAP, SMT, 0603, MLCC, 4.7µF, 10V, X7S, 10%,", Manufacturer=Murata, Manufacturer Part Number=GRM188C71A475KE11D, Operating Temperature=-55C~125C, Temp Coefficient=X7S, TOLERANCE=10%, Voltage=10V
C6 C31 C32 C39 C45: library part CMP-CAP-502-00167-1.9, "CAP, SMT, 0201, MLCC, 1uF, 10V, X6S, 20%", Manufacturer=Murata, Manufacturer Part Number=GRM033C81A105ME05#, Operating Temperature=-55C~105C, Temp Coefficient=X6S, TOLERANCE=20%, Voltage=10V
C7: library part CMP-CAP-502-00072-1.19, "CAP, SMT, 0201, MLCC, 15pF, 50V, C0G, 5%", Alt. Manufacturer=MURATA, Alt. Manufacturer Part Number=GRM0335C1H150JA01#, Manufacturer=Yageo, Manufacturer Part Number=CC0201JRNPO9BN150, Operating Temperature=-55C~125C, Temp Coefficient=C0G, TOLERANCE=5%, Voltage=50V
C11 C73 C74 C79 C80 C84 C85: library part CMP-CAP-502-00101-1.17, "CAP, SMT, 0402, MLCC, 1.0uF, 10V, X7S, 10%", Manufacturer=Murata, Manufacturer Part Number=GRM155C71A105KE11#, Operating Temperature=-55C~125C, Temp Coefficient=X7S, TOLERANCE=10%, Voltage=10V
C21: library part CMP-CAP-502-00063-1.16, "CAP, SMT, 0402, MLCC, 10nF, 50V, X7R, 10%", Manufacturer=Yageo, Manufacturer Part Number=CC0402KRX7R9BB103, Operating Temperature=-55C~125C, Temp Coefficient=X7R, TOLERANCE=10%, Voltage=50V
C33: library part CMP-CAP-502-00155-1.9, "CAP, SMT, 0201, MLCC, 2200pF, 16V, X7R, 10%", Manufacturer=Murata, Manufacturer Part Number=GRM033R71C222KA88#, Operating Temperature=-55C~125C, Temp Coefficient=X7R, TOLERANCE=10%, Voltage=16V
C38 C52: library part CMP-CAP-502-00046-1.12, "CAP, SMT, 0603, MLCC, 1.0uF, 10V, X7R, 10%,", Manufacturer=Murata, Manufacturer Part Number=GRM188R71A105KA61D, Operating Temperature=-55C~125C, Temp Coefficient=X7R, TOLERANCE=10%, Voltage=10V
C42 C43: library part CMP-CAP-502-00098-1.10, "CAP, SMT, 0603, MLCC, 4.7µF, 10V, X7S, 10%", Manufacturer=Murata, Manufacturer Part Number=GRM188C71A475KE11#, Operating Temperature=-55C~125C, Temp Coefficient=X7S, TOLERANCE=10%, Voltage=10V
C65 C66: library part CMP-CAP-502-00091-1.17, "CAP, SMT, 0402, MLCC, 300pF, 50V, COG/NPO, 5%,", Manufacturer=Walsin, Manufacturer Part Number=0402N301J500CT, Operating Temperature=-55C~125C, Temp Coefficient="C0G, NP0", TOLERANCE=5%, Voltage=50V
C75 C76: library part CMP-CAP-502-00116-1.16, "CAP, SMT, 0402, MLCC, 4.7uF, 6.3V, X6S, 20%", Manufacturer=Murata, Manufacturer Part Number=GRM155C80J475MEAA#, Operating Temperature=-55C~105C, Temp Coefficient=X6S, TOLERANCE=20%, Voltage=6.3V
C88 C89: library part CMP-CAP-502-00031-1.14, "CAP, SMT, 0201, MLCC, 10nF, 10V, X7R, 10%", Alt. Manufacturer=Murata, Alt. Manufacturer Part Number=GRM033R71A103K, Manufacturer=Walsin, Manufacturer Part Number=0201B103K100CT, Operating Temperature=-55C~125C, Temp Coefficient=X7R, TOLERANCE=10%, Voltage=10V
D1 D2: library part CMP-IC-510-00074-1.2, "IC, SMT, SOT23, Overvoltage-Suppressor,5V,400W,ESD-15KV-Air, 8KV-Contact, 3.3V~24V, 400W", Manufacturer=Panjit, Manufacturer Part Number=PJDLC05_R1_10001, Operating Temperature=-55C~125C, Supply Voltage=3.3V~24V
FB1 FB2: library part CMP-FB-505-00005-1.3, "FB, SMT, 0402, 120 Ohm @ 100MHz, 450mA, 190 mOhm,", Current=550mA, DC Resistance="190 mOhm", Impedance@Frequency="120 Ohm @ 100MHz", Manufacturer=Murata, Manufacturer Part Number=BLM15AG121SN1, Operating Temperature=-55C~125C
Fid1 Fid2 Fid3: library part CMP-MSC-SMT-WTS-522-0002-1.8, "Fiducial Mark"
J1: library part CMP-CON-130-00034-1.8, "CON, TH, Header, 2 pin, 2.54mm pitch, Male, Vertical", Manufacturer=Kingmate, Manufacturer Part Number=S110-S-02-2-60/25/30, Operating Temperature=-40C~105C, Voltage=1000V
J2 J3: library part CMP-CON-130-00120-1.4, "CON, TH, USB-C Type, 24 PIN, DIP+SMT 90d", Manufacturer=Kingconn, Manufacturer Part Number=7USB31-F0-0029, Operating Temperature=-25C~85C
J4: library part CMP-CON-130-00027-1.6, "CON, SMT/TH, Tag-Connect 2050, ,2 x5 , 3.175mm, PCB Footprint only", Manufacturer=Tag-Connect, Manufacturer Part Number=TC2050-IDC-NL
J7: library part CMP-CON-130-00213-1.1, "CON, SMT,Custom, FPC,1x5,1.20mm, NFC Connector", Manufacturer=Molex, Manufacturer Part Number=0512810598, Operating Temperature=-20C~85C
J45 P2 P20 P21 P22 P23 P24 P25 P29 P42: library part CMP-CON-130-00220-1.3, "CON, SMT, Header, 1X3 pins, 2.54mm pitch, Male, Vertical", Manufacturer=Kingmate, Manufacturer Part Number=S113-A-03-2-60/33-F0, Operating Temperature=-40C~105C
J58 J69: library part CMP-CON-130-00259-1.1, "CON, SMT, Vertical Header, 2X13 pins, 2.54mm pitch, Male, PHY 0.64mm", Manufacturer=Kingmate, Manufacturer Part Number=S123-T-26-2-60/33-F0, Operating Temperature=-40C~105C
J59: library part CMP-CON-130-00167-1.4, "CON, SMT, Wafer, 1x4, Pitch 1.0mm, Vertical", Manufacturer=WCON, Manufacturer Part Number=WF1001-WM04ER1, Operating Temperature=-25C~85C, Voltage=100V
J60 J61: library part CMP-CON-130-00168-1.2, "CON, SMT, Female Header, 2P54MM-1X8, Pitch 2.54mm, PHY 0.64mm", Alt. Manufacturer=Kingmate, Alt. Manufacturer Part Number=S214-B-08-2-89-F1, Manufacturer=WCON, Manufacturer Part Number=2185-108MG0CYNR2, Operating Temperature=-40C~105C
J70: library part CMP-CON-130-00255-1.1, "CON, SMT, Vertical Header, 2X11 pins, 2.54mm pitch, Male, PHY 0.64mm", Manufacturer=Kingmate, Manufacturer Part Number=S123-T-22-2-60/33-F0, Operating Temperature=-40C~105C
J71: library part CMP-CON-130-00256-1.1, "CON, SMT, Vertical Header, 2X9 pins, 2.54mm pitch, Male, PHY 0.64mm", Manufacturer=Kingmate, Manufacturer Part Number=S123-T-18-2-60/33-F0, Operating Temperature=-40C~105C
J72: library part CMP-CON-130-00257-1.1, "CON, SMT, Vertical Header, 2X7 pins, 2.54mm pitch, Male, PHY 0.64mm", Manufacturer=Kingmate, Manufacturer Part Number=S123-T-14-2-60/33-F0, Operating Temperature=-40C~105C
J73: library part CMP-CON-130-00253-1.0, "CON, SMT, Vertical  Header, Male Pin, 2x4, 2.54mm, PHY 0.64mm", Manufacturer=Kingmate, Manufacturer Part Number=S123-T-08-2-60/33-F0, Operating Temperature=-40°C~+105°C
JMP1 JMP2 JMP3 JMP4 JMP5 JMP6 JMP7 JMP8 JMP9 JMP10 JMP11 JMP12 JMP13 JMP14 JMP15 JMP16 JMP17 JMP18 JMP19 JMP20 JMP21 JMP22 JMP23 JMP24 JMP25 JMP26 JMP27 JMP28 JMP29 JMP30 JMP31 JMP32 JMP33 JMP34 JMP35 JMP36 JMP37 JMP38 JMP39 JMP40: library part CMP-CON-130-00121-1.11, "CON, TH, Pin header jumper CAP open type, Pitch 2.54mm,", Alt. Manufacturer=Any, Manufacturer=Kingmate, Manufacturer Part Number=S901D-1-1-E1, Operating Temperature=-40C~105C
L7 L10: library part CMP-IND-511-00164-1.1, "IND, SMT, 0806, Power Inductor, 2.2uH, 1.6A, 20%, 1MHz, 135 mOhm", Current=1.6A, DC Resistance="135 mOhm", Manufacturer="Wurth Elektronik", Manufacturer Part Number=74479276222C, Operating Temperature=-55C~125C, Test Frequency="1 MHz", TOLERANCE=20%
LED1 LED2 LED3 LED4 LED5: library part CMP-LED-521-00008-1.9, "LED, SMT, 0603, Blue, 2.7V, 10mA, 36mcd, 120 deg.", Alt. Manufacturer=Everlight, Alt. Manufacturer Part Number=19-217/BHC-ZL1M2TY/3T, Color=Blue, Current=10mA, Manufacturer Part Number=19-217/B7C-ZL2N1B3X/3T, Operating Temperature=-40C~85C
MH1 MH2 MH3 MH4: library part CMP-MSC-522-00015-1.2, "MSC, Mounting Hole, Hole 3.2mm, Dia 6mm"
MH5 MH6 MH7: library part CMP-MSC-522-00017-1.1, "MSC, Mounting Hole, Hole 1.524mm, Dia 1.524mm"
MOD1: library part CMP-MOD-453-00095-1.16, "MOD, SMT, BL54H20, Chip Antenna", Manufacturer=Ezurio, Manufacturer Part Number=453-00197
P1: library part CMP-CON-130-00030-1.8, "CON, TH, Header, 1x3, 1.25mm,", Manufacturer=Molex, Manufacturer Part Number=0530480310, Operating Temperature=-40C~105C, Voltage=125VAC/DC
P15 P19: library part CMP-CON-130-00112-1.1, "CON, SMT, Header, 2x5, Pitch 1.27mm, Vertical", Manufacturer=Kingmate, Manufacturer Part Number=N123-1-10-2-30/20/25/G1, Operating Temperature=-40C~105C
P16: library part CMP-CON-130-00048-1.7, "CON, SMT, Header, 2x10 pin, 1.27mm pitch, Male,", Manufacturer=Kingmate, Manufacturer Part Number=N123-1-20-2-30/20/25, Operating Temperature=-40C~105C, Voltage=1000V
P45: library part CMP-CON-130-00242-1.0, "CON, SMT, Header, 1X4 pins, 2.54mm pitch, Male, Vertical", Manufacturer=Kingmate, Manufacturer Part Number=S113-B-04-2-58/38-F0, Operating Temperature=-40C~105C
Q1 Q2 Q3 Q6 Q7 Q9 Q10: library part CMP-FET-506-00027-1.2, "FET, SMT, DFN1006-3, N-Channel, 20V, 1A, 470 mOhm, 1Vgs max", Current (Max)=1A, Manufacturer=Rohm, Manufacturer Part Number=RV2C010UNT2L, Operating Temperature=-55C~150C, Power Max (W)=400mW
Q4 Q5: library part CMP-FET-506-00031-1.0, "FET, SMT, DFN2020-6, Dual P-Channel, 20V, 3.8A, 90 mOhm, 0.9Vgs max", Current (Max)=3.8A, Manufacturer="Micro Commercial Components", Manufacturer Part Number=MCM2301-TP, Operating Temperature=-55C~150C, Power Max (W)=1.4W
R1 R11: library part CMP-RES-514-00319-1.1, "RES, SMT, 0201, Thick Film, 2.2, 1%, 0.05W", Alt. Manufacturer=Any, Manufacturer=Yageo, Manufacturer Part Number=RC0201FR-072R2L, Operating Temperature=-55C~125C, Power=0.05W, TOLERANCE=1%
R2: library part CMP-RES-514-00260-1.1, "RES, SMT, 0201, Thick Film, 47k, 1%, 0.05W", Alt. Manufacturer=Any, Manufacturer=Yageo, Manufacturer Part Number=RC0201FR-0747KL, Operating Temperature=-55C~125C, Power=0.05W, TOLERANCE=1%
R3 R10: library part CMP-RES-514-00018-1.29, "RES, SMT, 0201, Thick Film, 4.7k, 1%, 0.05W", Alt. Manufacturer=Any, Manufacturer=Yageo, Manufacturer Part Number=RC0201FR-074K7L, Operating Temperature=-55C~125C, Power=0.05W, TOLERANCE=1%
R4 R24 R25 R28 R43 R44 R50 R52 R53 R54 R55 R56 R57 R58 R59 R60 R61 R62 R63 R65 R66 R67 R70 R81 R83 R84 R85 R88 R95 R96 R97 R98 R99 R100 R101 R102 R103 R104 R105 R109 R110 R111 R112 R113 R114 R115 R120 R121 R122 R123: library part CMP-RES-514-00004-1.31, "RES, SMT, 0201, Thick Film, 0, 0.05W", Alt. Manufacturer=Any, Manufacturer=Yageo, Manufacturer Part Number=RC0201JR-070RL, Operating Temperature=-55C~125C, Power=0.05W, TOLERANCE=NA
R5: library part CMP-RES-514-00172-1.8, "RES, SMT, 0201, Thick Film, 1.0k, 5%, 0.05W", Alt. Manufacturer=Any, Manufacturer=YAGEO, Manufacturer Part Number=RC0201JR-071KL, Operating Temperature=-55C~125C, Power=0.05W, TOLERANCE=5%
R6 R8 R9 R15 R16 R17 R18 R19 R22 R23 R27 R36 R40 R80 R82 R86 R87 R89 R92 R93 R94 R108 R116: library part CMP-RES-514-00064-1.24, "RES, SMT, 0201, Thick Film, 100k, 1%, 0.05W", Alt. Manufacturer=Any, Manufacturer=Yageo, Manufacturer Part Number=RC0201FR-07100KL, Operating Temperature=-55C~125C, Power=0.05W, TOLERANCE=1%
R7: library part CMP-RES-514-00108-1.13, "RES, SMT, 0201, Thick Film, 49.9, 1%, 0.05W", Alt. Manufacturer=Any, Manufacturer=Yageo, Manufacturer Part Number=RC0201FR-0749R9L, Operating Temperature=-55C~125C, Power=0.05W, TOLERANCE=1%
R12 R13 R14 R26 R38 R64 R75 R76 R77 R78 R91 R106 R107 R117 R118 R119: library part CMP-RES-514-00247-1.2, "RES, SMT, 0201, Thick Film, 10k, 1%, 0.05W", Alt. Manufacturer=Any, Manufacturer=Yageo, Manufacturer Part Number=RC0201FR-7D10KL, Operating Temperature=-55C~125C, Power=0.05W, TOLERANCE=1%
R20 R21 R68 R69: library part CMP-RES-514-00068-1.17, "RES, SMT, 0201, Thick Film, 1.2k, 5%, 0.05W", Alt. Manufacturer=Any, Manufacturer=Yageo, Manufacturer Part Number=RC0201JR-071K2L, Operating Temperature=-55C~125C, Power=0.05W, TOLERANCE=5%
R29: library part CMP-RES-514-00326-1.1, "RES, SMT, 0201, Thick Film, 270k, 1%, 0.05W, 25V", Alt. Manufacturer=Any, Manufacturer=Yageo, Manufacturer Part Number=RC0201FR-07270KL, Operating Temperature=-55C~125C, Power=0.05W, TOLERANCE=1%
R30 R31 R34 R35 R37 R39 R41 R51: library part CMP-RES-514-00140-1.10, "RES, SMT, 0402, Thick Film, 10, 5%, 0.0625W", Alt. Manufacturer=Any, Manufacturer=Yageo, Manufacturer Part Number=RC0402JR-0710RL, Operating Temperature=-55C~125C, Power=0.0625W, TOLERANCE=5%
R32 R42 R71 R72 R73 R74 R79: library part CMP-RES-514-00017-1.28, "RES, SMT, 0201, Thick Film, 1M, 1%, 0.05W", Alt. Manufacturer=Any, Manufacturer=Yageo, Manufacturer Part Number=RC0201FR-071ML, Operating Temperature=-55C~125C, Power=0.05W, TOLERANCE=1%
R33 R48: library part CMP-RES-514-00333-1.2, "RES, SMT, 0402, Thick Film, 18.2k, 1%, 0.0625W", Alt. Manufacturer=Any, Manufacturer=Yageo, Manufacturer Part Number=RC0402FR-0718K2L, Operating Temperature=-55C~155C, Power=0.0625W, TOLERANCE=1%
R45 R46 R47 R49: library part CMP-RES-514-00342-1.0, "RES, SMT, 0201, Thick Film, 5.1k, 1%, 0.05W", Alt. Manufacturer=Any, Manufacturer=Yageo, Manufacturer Part Number=RC0201FR-075K1L, Operating Temperature=-55C~125C, Power=0.05W, TOLERANCE=1%
R90: library part CMP-RES-514-00293-1.1, "RES, SMT, 0201, Thick Film, 31.6k, 1%, 0.05W", Alt. Manufacturer=Any, Manufacturer=Yageo, Manufacturer Part Number=RC0201FR-0731K6L, Operating Temperature=-55C~125C, Power=0.05W, TOLERANCE=1%
S1 SW1 SW2 SW3 SW5 SW6: library part CMP-SW-516-00005-1.12, "SW, SMT, Tact, Vertical, Momentary On, 6mm x 6mm x 4.3mm", Manufacturer=Touke, Manufacturer Part Number=TS-06M-ASM-T-T/R, Operating Temperature=-40C-85C, Voltage Rating AC/DC="500VAC-1 minute"
SB1 SB3 SB5: library part CMP-Misc-522-00003-1.9, "MSC, Solderbridge Open"
SB2 SB4 SB6 SB7: library part CMP-Misc-522-00004-1.17, "MSC, Solderbridge Closed"
SW4: library part CMP-SW-516-00040-1.0, "SW, SMD, Slide, DPDT, On, On, 6VDC, 300mA", Current Rating=300mA, Manufacturer=C&K, Manufacturer Part Number=JS202011SCQN, Operating Temperature=-40C~85C, Voltage Rating AC/DC=6V
SW7 SW8 SW9 SW10: library part CMP-SW-516-00015-1.3, "SW, SMD, Slide, 1P2T, 4VDC, 0.3A", Current Rating=0.3A, Manufacturer=Contact, Manufacturer Part Number=SS-B95A-W-S246, Operating Temperature=-40C~85C, Voltage Rating AC/DC=4V
TP1 TP2 TP3 TP4 TP5 TP7 TP8 TP9 TP10 TP11 TP12 TP13 TP14 TP15 TP16 TP17 TP18 TP19 TP20 TP35 TP36 TP37 TP38 TP39 TP40 TP41 TP42 TP45 TP46 TP51 TP52 TP58 TP59 TP60 TP61 TP62 TP73 TP82 TP87 TP88: library part CMP-MSC-522-00070-1.0, "MSC, SMT, 1.5mm, Test Pad"
TP21 TP22 TP23 TP24 TP25 TP26 TP27 TP28 TP29 TP30 TP31 TP32 TP33 TP34 TP84: library part CMP-MSC-522-00071-1.0, "MSC, SMT, 0.7mm, Test Pad"
U1 U16 U20: library part CMP-IC-510-00397-1.1, "IC, SMT, 5-TSOP, LDO Voltage Regulators, 300mA, 1.8V", Manufacturer="On Semiconductor", Manufacturer Part Number=NCV8114ASN180T1G, Operating Temperature=-40C~125C, Supply Current=300mA, Supply Voltage=1.8V
U2: library part CMP-IC-510-00161-1.5, "IC, SMT, aQFN-94(7x7), Multi-protocol Bluetooth Low Energy, IEEE 802.15.4, ANT and 2.4GHz proprietary system-on-chip", Manufacturer="Nordic Semiconductor", Manufacturer Part Number=nRF5340-QKAA, Operating Temperature=-40C~105C, Supply Current=80mA, Supply Voltage=1.7V~5.5V
U3 U4 U5 U6 U7 U8: library part CMP-IC-510-00382-1.0, "IC, SMT, X2SON-8, 2-Bit Bidirectional Voltage-Level Translator with Automatic Direction Sensing, 0.9V~3.6V", Manufacturer="Texas Instruments", Manufacturer Part Number=TXB0302DQMR, Operating Temperature=-40C~85C, Supply Voltage=0.9V~3.6V
U9: library part CMP-IC-510-00341-1.1, "IC, SMT, SOT25, 1.0x1.5mm, Power Switch/Driver 1:1 N-Channel, 1.1V~5.5V, 3A", Manufacturer=Toshiba, Manufacturer Part Number=TCK111G,LF, Operating Temperature=-40C~85C, Supply Current=3A, Supply Voltage=1.1V~5.5V
U10 U21: library part CMP-IC-510-00240-1.3, "IC, SMT, VSSOP8, Bidirectional, 2-Bit, Level Translator with auto-direction sensing, 1.2V~5.5V, 8uA", Manufacturer="Texas Instruments", Manufacturer Part Number=TXB0102DCUR, Operating Temperature=-40C~85C, Supply Current=8uA, Supply Voltage=1.2V~5.5V
U11: library part CMP-IC-510-00396-1.1, "IC, SMT, TFBGA24, NOR Flash Memory, 64Mb (8M x 8) SPI - Octa I/O, DTR 200MHz, 1.7V~2V", Manufacturer=Macronix, Manufacturer Part Number=MX25UW6345GXDI00, Operating Temperature=-40C~125C, Supply Voltage=1.7V~2V
U12: library part CMP-IC-510-00351-1.4, "IC, SMT, QFN32, PMIC, 4V~5.5V", Manufacturer="Nordic Semiconductor", Manufacturer Part Number=nPM1300-QEAA, Operating Temperature=-40C~125C, Supply Voltage=4V~5.5V
U13: library part CMP-IC-510-00070-1.1, "IC, SMT, UQFN16, Data / Audio Low-Voltage dual DPDT analog switch, 1.65~4.45V, -40C~85C", Manufacturer="ON Semi", Manufacturer Part Number=FSA2466UMX, Operating Temperature=-40C~85C, Supply Voltage=1.65V~4.45V
U14: library part CMP-IC-510-00072-1.5, "IC, SMT, SOT23-5, Reg LDO, 2.5~5.5V, Output 3.3V 600mA", Manufacturer=Richtek, Manufacturer Part Number=RT9187BGB, Operating Temperature=-40C~85C, Supply Voltage=2.5V~5.5V
U15: library part CMP-IC-510-00103-1.2, "IC, SMT, SC70-5, Single Power Supply Single Buffer GATE CMOS Logic Level Shifter", Manufacturer="Texas Instruments", Manufacturer Part Number=SN74LV1T34DCKR, Operating Temperature=-40C~125C, Supply Current=8mA, Supply Voltage=1.6V~5.5V
U22: library part CMP-IC-510-00008-1.6, "IC, SMT,  TSSOP14, Logic Translator, 1.65V~5.5V", Manufacturer="Texas Instruments", Manufacturer Part Number=TXB0104PWR, Operating Temperature=-40C~85C, Supply Current=100mA, Supply Voltage=1.65V~5.5V
U23: library part CMP-IC-510-00320-1.6, "IC, SMT, 8-UFBGA, DSBGA, Level Shifter,1.65 V ~ 3.6 V, ,", Manufacturer=TI, Manufacturer Part Number=TXS0102YZPR, Operating Temperature=-40C~85C, Supply Current=NA, Supply Voltage="1.65 V ~ 3.6 V"
X2: library part CMP-XTL-524-00025-1.1, "XTL, SMT, 2 pin, 2.0mm x 1.2mm, 32.768KMHz, 20ppm, 80 kOhm, 9pF", Frequency=32.768KMHz, Load Capacitance=9pF, Manufacturer=Siward, Manufacturer Part Number=XTL741-S999-506, Operating Temperature=-40C~105C, TOLERANCE=20ppm
X3: library part CMP-XTL-524-00010-1.5, "XTL, SMT, 4 pin, 1.2mm x 1.6mm, 32MHz, 15ppm, 60 Ohm, 8pF", Frequency=32.000000MHz, Load Capacitance=8pF, Manufacturer=Siward, Manufacturer Part Number=XTL901200-L146-014, Operating Temperature=-40C~105C, TOLERANCE=15ppm

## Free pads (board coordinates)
  round 4 hole 4 unplated mask+0.254: 0(-5.996,-6) 0(-5.996,135) 0(154.609,-6) 0(154.609,135)
  round 1 smd paste-10 mask+0.254: 0(30.004,135) 0(50.004,-6) 0(111.609,-6) 0(111.609,135)
  round 1 smd far side paste-10 mask+0.254: 0(30.004,135) 0(50.004,-6) 0(111.609,-6) 0(111.609,135)
  round 3.2 hole 3.2 unplated: 1(7.995,5) 1(12.595,58.5) 1(43.995,5) 1(43.995,58.5) 1(138.609,5) 1(138.609,58.5)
